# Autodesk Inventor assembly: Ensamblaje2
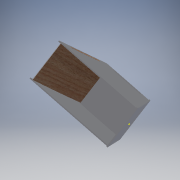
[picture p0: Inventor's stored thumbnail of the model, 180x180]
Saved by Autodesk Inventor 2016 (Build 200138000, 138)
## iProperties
Created: 2016-06
Part Number: Ensamblaje2
Material: Genérico
Document SubType Name: Assembly
Designer: adm
Author: adm
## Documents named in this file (5)
- C:\Users\adm\Desktop\recepcion 2\Ensamblaje2.iam
- C:\Users\adm\Desktop\recepcion 2\parte porterior.ipt
- C:\Users\adm\Desktop\recepcion 2\lado inclinado.ipt
- C:\Users\adm\Desktop\recepcion 2\base.ipt
- C:\Users\adm\Desktop\recepcion 2\laterales.ipt
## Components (5 placed, 4 different names)
1. parte porterior:1 — Nivelación:2, Coincidencia:10, Nivelación:3, Coincidencia:11, Coincidencia:12, Nivelación:4, Coincidencia:13, Coincidencia:14, Coincidencia:15, Nivelación:5
2. lado inclinado:1 — Coincidencia:20, Nivelación:7
3. base:1 — Nivelación:2, Coincidencia:10, Nivelación:3, Coincidencia:11, Coincidencia:14, Coincidencia:15, Coincidencia:16, Coincidencia:17, Coincidencia:18, Coincidencia:19, Nivelación:6
4. laterales:1 — Coincidencia:12, Nivelación:4, Coincidencia:13, Coincidencia:19, Nivelación:6
5. laterales:2 — Coincidencia:16, Coincidencia:17, Coincidencia:18, Nivelación:5, Coincidencia:20, Nivelación:7
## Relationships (17: Mate 11, Flush 6)
- Nivelación:2 [Flush]: parte porterior:1 ↔ base:1
- Coincidencia:10 [Mate]: parte porterior:1 ↔ base:1
- Nivelación:3 [Flush]: parte porterior:1 ↔ base:1
- Coincidencia:11 [Mate]: parte porterior:1 ↔ base:1
- Coincidencia:12 [Mate]: parte porterior:1 ↔ laterales:1
- Nivelación:4 [Flush]: parte porterior:1 ↔ laterales:1
- Coincidencia:13 [Mate]: parte porterior:1 ↔ laterales:1
- Coincidencia:14 [Mate]: parte porterior:1 ↔ base:1
- Coincidencia:15 [Mate]: parte porterior:1 ↔ base:1
- Coincidencia:16 [Mate]: base:1 ↔ laterales:2
- Coincidencia:17 [Mate]: base:1 ↔ laterales:2
- Coincidencia:18 [Mate]: base:1 ↔ laterales:2
- Coincidencia:19 [Mate]: base:1 ↔ laterales:1
- Nivelación:5 [Flush]: parte porterior:1 ↔ laterales:2
- Nivelación:6 [Flush]: base:1 ↔ laterales:1
- Coincidencia:20 [Mate]: lado inclinado:1 ↔ laterales:2
- Nivelación:7 [Flush]: lado inclinado:1 ↔ laterales:2
